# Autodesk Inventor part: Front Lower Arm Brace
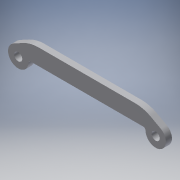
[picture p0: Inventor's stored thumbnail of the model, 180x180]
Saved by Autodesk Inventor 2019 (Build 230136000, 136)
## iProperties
Shininess: 20.0
Compacted: True
Length Units: 11272
Angle Units: 11279
Time Units: 11290
Mass Units: 11286
Length Display Precision: 3
Angle Display Precision: 2
Company: Autodesk
Created: 2001-02
Part Number: Front Lower Arm Brace
Document SubType Name: Modeling
Designer: Autodesk, Inc.
Project: Inventor Samples
Density: 2.71 g/cm^3
Mass: 2.54875 g
Surface Area: 11.6999 cm^2
Volume: 0.940497 cm^3
Material: Aluminum-6061
Appearance: Aluminum - Flat
Density: 0.0
Volumn: 0.0
Area: 0.0
PropertySet Name: Model Information
Control State: 0
Master: False
Checked Out: False
Checked Out Date: 2018-05-30
Last Check In Date: 2018-05-30
Author: Autodesk, Inc.
Revision Number: A
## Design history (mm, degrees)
sketch "Sketch1"
  geometry: L1 (-23.139, -2.357)-(22.708, -2.357); L2 (-23.139, -3.132)-(-23.139, -2.357); L3 (22.708, -3.132)-(22.708, -2.357); L4 (-29.057, 0.379)-(-22.44, 3.993); L5 (-22.44, 3.993)-(22.01, 3.993); L6 (22.01, 3.993)-(28.626, 0.379); C1 r 1.587 at (-27.139, -3.132); C2 r 1.587 at (26.709, -3.132); A1 r 4.001 centre (-27.139, -3.132) between (-29.057, 0.379) and (-23.139, -3.132); A2 r 4.001 centre (26.709, -3.132) between (22.708, -3.132) and (28.626, 0.379)
  constraints: 12 end point, 4 centre point, 4 point on circle, 4 tangent, 2 coincident, 2 equal radius, 2 perpendicular, 1 equal length, 1 horizontal, 1 horizontal alignment, 1 parallel, 1 other
  dimensions: "d0" = 4.7752 dimension on A1 L1; "d1" = 8.001 diameter of A1; "d2" = 6.35 distance between parallel lines of L5 L1; "d3" = 44.45 distance of L4.end L5.end; "d4" = 53.848 distance of A2.centre A1.centre; "d5" = 3.175 diameter of C1
extrude "Extrusion1" new body sketch "Sketch1" distance "d6" = 2.38125; taper "d7" = 0 deg
fillet "Fillet1" dims "d8" = 12.7
fillet "Fillet2" dims "d9" = 0.8128
body "Solid1"
